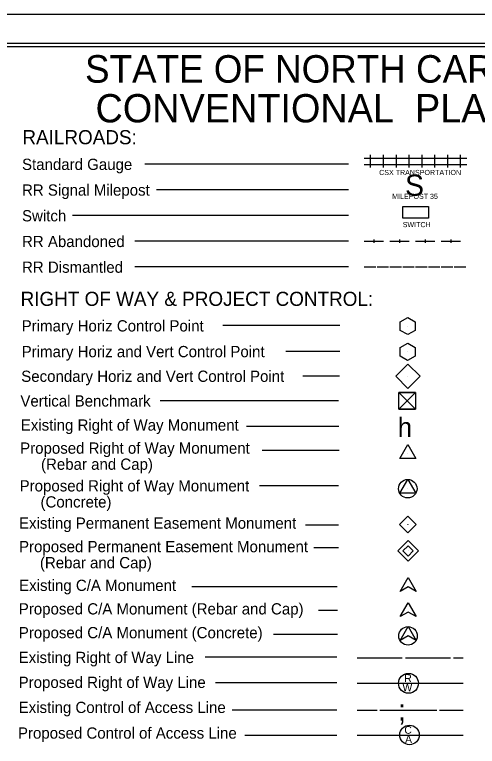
# Model space of a CAD drawing. Extents: x 147589369 to 147592737, y 91898723 to 91900923.
# Drawn here: x 147590495 to 147591216, y 91899785 to 91900923 of the extents above; entities that cross this region are included whole.
import ezdxf

# ---------------------------------------------------------------- set-up
doc = ezdxf.new("R2010")
doc.units = 0
for name, color, linetype in [('Default', 7, 'Continuous'), ('Prop ROW Permanent Easement CELL', 7, 'Continuous'), ('Sheet Cutting Line CELL', 7, 'Continuous'), ('Sheet Plot Border Inside CELL', 7, 'Continuous'), ('Sheet Plot Border Outside CELL', 7, 'Continuous'), ('Sheet Symbology CELL', 7, 'Continuous')]:
    doc.layers.add(name, color=color, linetype=linetype)

msp = doc.modelspace()

# ---------------------------------------------------------------- linework, layer by layer
at = {"layer": 'Default'}
for p, q in [((147591107, 91900438.5), (147591107, 91900438.5)), ((147591107, 91900398.5), (147591107, 91900398.5)), ((147591107.3, 91900360.4), (147591107.3, 91900360.4)), ((147591106.3, 91900322.4), (147591106.3, 91900322.4)), ((147591107.2, 91900129.9), (147591107.2, 91900129.9))]:
    msp.add_line(p, q, dxfattribs=at)
for points in [[(147591107, 91900425.2), (147591095.4, 91900431.7), (147591095.4, 91900445.1), (147591107, 91900451.8), (147591118.6, 91900445.2), (147591118.6, 91900431.7), (147591107, 91900425.2)], [(147591119.2, 91900335.3), (147591093.3, 91900309.4), (147591106.3, 91900322.4), (147591119.2, 91900309.4), (147591093.3, 91900335.3)], [(147591106.3, 91900322.4), (147591119.2, 91900335.3), (147591093.3, 91900335.3), (147591106.3, 91900322.4)], [(147591106.3, 91900322.4), (147591093.3, 91900309.4), (147591119.2, 91900309.4), (147591106.3, 91900322.4)]]:
    msp.add_lwpolyline(points, dxfattribs=at)
for points in [[(147591095.4, 91900405.3), (147591107.1, 91900411.8), (147591118.8, 91900405.4), (147591118.6, 91900391.9), (147591106.9, 91900385.1), (147591095.4, 91900391.7)], [(147591088.5, 91900360.4), (147591107.4, 91900379.4), (147591126.3, 91900360.4), (147591107.4, 91900341.5)], [(147591093.3, 91900335.3), (147591119.2, 91900335.3), (147591119.2, 91900309.4), (147591093.3, 91900309.4)], [(147591094.2, 91900129.9), (147591107.2, 91900142.9), (147591120.2, 91900129.9), (147591107.2, 91900117)]]:
    msp.add_lwpolyline(points, close=True, dxfattribs=at)
msp.add_circle((147591107.2, 91900129.9), 0.253, dxfattribs=at)
at = {"layer": 'Prop ROW Permanent Easement CELL'}
msp.add_line((147591107.6, 91900088.7), (147591107.6, 91900088.7), dxfattribs=at)
for points in [[(147591107.6, 91900104.8), (147591123.7, 91900088.7), (147591107.6, 91900072.6), (147591091.5, 91900088.7)], [(147591107.6, 91900096.8), (147591115.6, 91900088.7), (147591107.6, 91900080.7), (147591099.5, 91900088.7)]]:
    msp.add_lwpolyline(points, close=True, dxfattribs=at)
at = {"layer": 'Sheet Cutting Line CELL'}
msp.add_line((147592737.3, 91900923.1), (147589369.3, 91900923.1), dxfattribs=at)
at = {"layer": 'Sheet Plot Border Inside CELL'}
msp.add_lwpolyline([(147589395.3, 91898768), (147592728.3, 91898768), (147592728.3, 91900878.2), (147589395.3, 91900878.2)], close=True, dxfattribs=at)
at = {"layer": 'Sheet Plot Border Outside CELL'}
msp.add_lwpolyline([(147589369.3, 91898723.1), (147592737.3, 91898723.1), (147592737.3, 91900923.1), (147589369.3, 91900923.1)], close=True, dxfattribs=at)
at = {"layer": 'Sheet Symbology CELL'}
for p, q in [((147591049.3, 91900685), (147591049.3, 91900705)), ((147591069.3, 91900685), (147591069.3, 91900705)), ((147591089.3, 91900685), (147591089.3, 91900705)), ((147591109.3, 91900685), (147591109.3, 91900705)), ((147591129.3, 91900685), (147591129.3, 91900705)), ((147591149.3, 91900685), (147591149.3, 91900705)), ((147591169.3, 91900685), (147591169.3, 91900705)), ((147591189.3, 91900685), (147591189.3, 91900705)), ((147591014.6, 91900690.5), (147590697.7, 91900690.5)), ((147591039.3, 91900700), (147591059.3, 91900700)), ((147591059.3, 91900700), (147591079.3, 91900700)), ((147591079.3, 91900700), (147591099.3, 91900700)), ((147591099.3, 91900700), (147591119.3, 91900700)), ((147591119.3, 91900700), (147591139.3, 91900700)), ((147591139.3, 91900700), (147591159.3, 91900700)), ((147591159.3, 91900700), (147591179.3, 91900700)), ((147591179.3, 91900700), (147591199.3, 91900700)), ((147591039.3, 91900690), (147591059.3, 91900690)), ((147591059.3, 91900690), (147591079.3, 91900690)), ((147591079.3, 91900690), (147591099.3, 91900690)), ((147591099.3, 91900690), (147591119.3, 91900690)), ((147591119.3, 91900690), (147591139.3, 91900690)), ((147591139.3, 91900690), (147591159.3, 91900690)), ((147591159.3, 91900690), (147591179.3, 91900690)), ((147591179.3, 91900690), (147591199.3, 91900690)), ((147591014.6, 91900650.5), (147590715.5, 91900650.5)), ((147591014.6, 91900610.5), (147590584.7, 91900610.5)), ((147591014.6, 91900570.5), (147590682.2, 91900570.5)), ((147591039.3, 91900570.5), (147591069.3, 91900570.5)), ((147591054.3, 91900573), (147591054.3, 91900568)), ((147591079.3, 91900570.5), (147591109.3, 91900570.5)), ((147591094.3, 91900573), (147591094.3, 91900568)), ((147591119.3, 91900570.5), (147591149.3, 91900570.5)), ((147591134.3, 91900573), (147591134.3, 91900568)), ((147591159.3, 91900570.5), (147591189.3, 91900570.5)), ((147591174.3, 91900573), (147591174.3, 91900568)), ((147591014.6, 91900530.5), (147590682.2, 91900530.5)), ((147591014.6, 91900530.5), (147590682.2, 91900530.5)), ((147591039.3, 91900530.5), (147591057.3, 91900530.5)), ((147591059.3, 91900530.5), (147591077.3, 91900530.5)), ((147591079.3, 91900530.5), (147591097.3, 91900530.5)), ((147591099.3, 91900530.5), (147591117.3, 91900530.5)), ((147591119.3, 91900530.5), (147591137.3, 91900530.5)), ((147591139.3, 91900530.5), (147591157.3, 91900530.5)), ((147591159.3, 91900530.5), (147591177.3, 91900530.5)), ((147591179.3, 91900530.5), (147591197.3, 91900530.5)), ((147591001.2, 91900439.2), (147590819.1, 91900439.2)), ((147591001.2, 91900399.2), (147590917.3, 91900399.2)), ((147591000.5, 91900360.8), (147590943.4, 91900360.8)), ((147590999.2, 91900322.4), (147590721.5, 91900322.4)), ((147590999.8, 91900282.4), (147590855.7, 91900282.4)), ((147591000, 91900244.8), (147590880.5, 91900244.8)), ((147591107, 91900239.6), (147591107, 91900239.6)), ((147590999, 91900190), (147590876, 91900190)), ((147591107.1, 91900185.5), (147591107.1, 91900185.5)), ((147590999.1, 91900128.6), (147590947.6, 91900128.6)), ((147590999.1, 91900093.4), (147590960.6, 91900093.4)), ((147591095, 91900025.6), (147591107.5, 91900047.2)), ((147591107.5, 91900047.2), (147591120, 91900025.6)), ((147590997.2, 91900033), (147590770.7, 91900033)), ((147591107.5, 91900032.8), (147591095, 91900025.6)), ((147591120, 91900025.6), (147591107.5, 91900032.8)), ((147591095, 91899986.4), (147591107.5, 91900008)), ((147591107.5, 91900008), (147591120, 91899986.4)), ((147590997.4, 91899995.9), (147590968.2, 91899995.9)), ((147591107.5, 91899993.6), (147591095, 91899986.4)), ((147591120, 91899986.4), (147591107.5, 91899993.6)), ((147591095, 91899949.3), (147591107.5, 91899970.9)), ((147591107.5, 91899970.9), (147591120, 91899949.3)), ((147590997.4, 91899958.9), (147590898, 91899958.9)), ((147591107.5, 91899956.5), (147591095, 91899949.3)), ((147591120, 91899949.3), (147591107.5, 91899956.5)), ((147590996.5, 91899923.3), (147590791.4, 91899923.3)), ((147591028.5, 91899922.2), (147591098.5, 91899922.2)), ((147591103.5, 91899922.2), (147591173.5, 91899922.2)), ((147591178.5, 91899922.2), (147591193.5, 91899922.2)), ((147590996.5, 91899883.3), (147590807.4, 91899883.3)), ((147591028.5, 91899883.1), (147591193.5, 91899883.1)), ((147590996.5, 91899841.1), (147590833.8, 91899841.1)), ((147591028.5, 91899841.1), (147591059.5, 91899841.1)), ((147591063.5, 91899841.1), (147591152.3, 91899841.1)), ((147591156.3, 91899841.1), (147591193.5, 91899841.1)), ((147590996.5, 91899801.4), (147590853.2, 91899801.4)), ((147591028.5, 91899802.2), (147591193.5, 91899802.2))]:
    msp.add_line(p, q, dxfattribs=at)
for points in [[(147592703.3, 91900873.1), (147589703.3, 91900873.1), (147589703.3, 91898775.1), (147592703.3, 91898775.1)], [(147591099.3, 91900624.4), (147591139.3, 91900624.4), (147591139.3, 91900606.2), (147591099.3, 91900606.2)], [(147591094.5, 91900232.4), (147591107, 91900254), (147591119.5, 91900232.4)], [(147591094.6, 91900178.3), (147591107.1, 91900199.9), (147591119.6, 91900178.3)]]:
    msp.add_lwpolyline(points, close=True, dxfattribs=at)
for centre, radius in [((147591107.1, 91900185.5), 14.4), ((147591107.5, 91899956.5), 14.4), ((147591108.2, 91899882.7), 15.5), ((147591109.8, 91899802.4), 15.2)]:
    msp.add_circle(centre, radius, dxfattribs=at)

# ---------------------------------------------------------------- texts
for s, height, p in [('STATE OF NORTH CAROLINA, DIVISION OF HIGHWAYS', 42.838, (147590604.4, 91900817.2)), ('CONVENTIONAL  PLAN SHEET SYMBOLS', 44.065, (147590620.7, 91900755.4)), ('RAILROADS:', 22, (147590506.8, 91900721.4)), ('Standard Gauge', 17.5, (147590506.2, 91900681.4)), ('S', 33, (147591102.9, 91900641.2)), ('RR Signal Milepost', 17.5, (147590506.2, 91900641.4)), ('Switch', 17.5, (147590506.2, 91900601.4)), ('RR Abandoned', 17.5, (147590506.2, 91900561.4)), ('RR Dismantled', 17.5, (147590506.2, 91900521.4)), ('RIGHT OF WAY & PROJECT CONTROL:', 22, (147590504, 91900469.9)), ('Primary Horiz Control Point', 17.5, (147590505.7, 91900430.1)), ('Primary Horiz and Vert Control Point', 17.5, (147590505.7, 91900390.1)), ('Secondary Horiz and Vert Control Point', 17.5, (147590505, 91900351.7)), ('Vertical Benchmark', 17.5, (147590503.7, 91900313.3)), ('Existing Right of Way Monument', 17.5, (147590504.3, 91900275.8)), ('h', 30, (147591091.5, 91900266)), ('Proposed Right of Way Monument', 17.5, (147590503.3, 91900239.9)), ('     (Rebar and Cap)', 17.5, (147590503.3, 91900214.9)), ('Proposed Right of Way Monument', 17.5, (147590502.5, 91900181.2)), ('     (Concrete)', 17.5, (147590502.5, 91900156.2)), ('Existing Permanent Easement Monument', 17.5, (147590501.5, 91900123.2)), ('Proposed Permanent Easement Monument', 17.5, (147590501.6, 91900086.7)), ('     (Rebar and Cap)', 17.5, (147590501.6, 91900061.7)), ('Existing C/A Monument', 17.5, (147590501.7, 91900026.4)), ('Proposed C/A Monument (Rebar and Cap)', 17.5, (147590501.2, 91899989.8)), ('Proposed C/A Monument (Concrete)', 17.5, (147590501.2, 91899952.8)), ('Existing Right of Way Line', 17.5, (147590501, 91899914.2)), ('Proposed Right of Way Line', 17.5, (147590501, 91899875.5)), ('R', 12.2, (147591101.6, 91899884.5)), ('W', 12.2, (147591098.8, 91899870.2)), ('Existing Control of Access Line', 17.5, (147590501, 91899836.5)), (';', 33, (147591092.1, 91899824.7)), ('Proposed Control of Access Line', 17.5, (147590499.9, 91899796.6)), ('C', 11.9, (147591101.8, 91899804.2)), ('A', 11.9, (147591103, 91899789.9))]:
    msp.add_text(s, height=height, dxfattribs=at).set_placement(p)
for s, p in [('CSX TRANSPORTATION', (147591062.5, 91900673.5)), ('MILEPOST 35', (147591082.8, 91900636.4)), ('SWITCH', (147591099.2, 91900592.4))]:
    msp.add_text(s, height=8, rotation=360, dxfattribs=at).set_placement(p)

doc.saveas('drawing.dxf')
